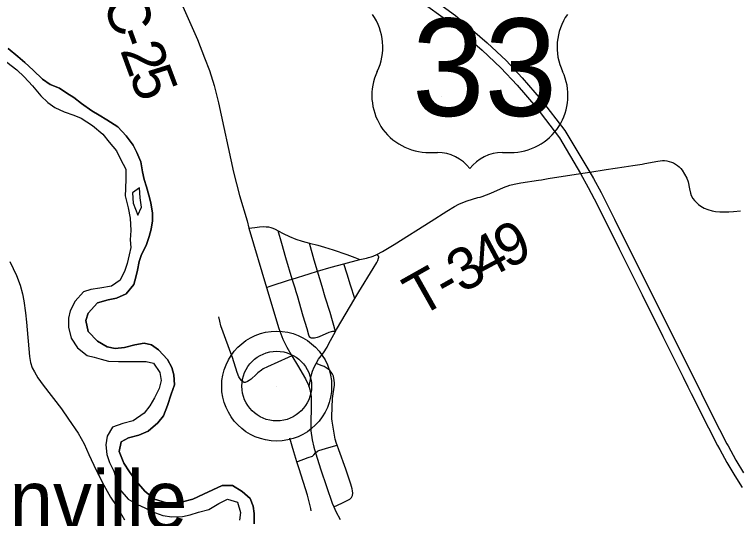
# Model space of a CAD drawing. Extents: x 0 to 34, y 0 to 22.
# Drawn here: x 6.535 to 7.513, y 19.145 to 19.828 of the extents above; entities that cross this region are included whole.
import ezdxf

# ---------------------------------------------------------------- set-up
doc = ezdxf.new("R2010")
doc.units = 0
for name, color, linetype in [('GM_X_County_Road', 7, 'Continuous'), ('GM_X_County_Road_Text', 7, 'Continuous'), ('GM_X_Major_River', 7, 'Continuous'), ('GM_X_Township_Road', 7, 'Continuous'), ('GM_X_Township_Road_Text', 7, 'Continuous'), ('GM_X_Unincorporated', 7, 'Continuous'), ('GM_X_Unincorporated_Location', 7, 'Continuous'), ('GM_X_Unincorporated_Text', 7, 'Continuous'), ('GM_X_US_Location', 7, 'Continuous'), ('GM_X_US_Route', 7, 'Continuous'), ('GM_X_US_Shield', 7, 'Continuous')]:
    doc.layers.add(name, color=color, linetype=linetype)

msp = doc.modelspace()

# ---------------------------------------------------------------- linework, layer by layer
at = {"layer": 'GM_X_County_Road'}
for points in [[(6.7422, 20.01268), (6.73349, 19.99257), (6.72983, 19.98078), (6.72724, 19.96871), (6.72574, 19.95646), (6.72526, 19.94412), (6.72589, 19.9318), (6.72779, 19.91962), (6.73082, 19.90765), (6.73703, 19.89336), (6.74215, 19.88192), (6.74814, 19.87005), (6.76059, 19.84248), (6.78228, 19.79398), (6.79191, 19.76888)], [(6.79191, 19.76888), (6.79833, 19.75214), (6.80482, 19.73182), (6.81063, 19.70809), (6.83112, 19.61417), (6.83931, 19.58275), (6.84956, 19.54826), (6.8518, 19.53845), (6.87567, 19.45833), (6.89225, 19.40271), (6.89759, 19.38823), (6.90302, 19.37716), (6.91006, 19.36545), (6.9174, 19.35322), (6.92859, 19.33449), (6.9326, 19.32597), (6.9331, 19.32438), (6.93449, 19.31993), (6.93587, 19.31056), (6.93617, 19.29805), (6.93544, 19.27322), (6.93577, 19.26399), (6.93743, 19.25177), (6.93979, 19.24193), (6.94181, 19.23412), (6.94937, 19.21129), (6.96439, 19.16599), (6.96661, 19.16101), (6.9694, 19.15472), (6.97549, 19.14401)]]:
    msp.add_lwpolyline(points, dxfattribs=at)
at = {"layer": 'GM_X_Major_River'}
for p, q in [((6.53895, 19.77098), (6.52599, 19.78185)), ((6.54848, 19.76273), (6.53895, 19.77098)), ((6.52426, 19.76327), (6.5376, 19.75278)), ((6.55992, 19.75222), (6.54848, 19.76273)), ((6.5376, 19.75278), (6.54752, 19.74339)), ((6.57252, 19.74021), (6.55992, 19.75222)), ((6.54752, 19.74339), (6.55897, 19.73137)), ((6.58279, 19.73311), (6.57252, 19.74021)), ((6.55897, 19.73137), (6.57006, 19.71783)), ((6.59532, 19.72792), (6.58279, 19.73311)), ((6.60522, 19.72118), (6.59532, 19.72792)), ((6.61473, 19.71559), (6.60522, 19.72118)), ((6.57006, 19.71783), (6.5796, 19.70845)), ((6.62539, 19.70735), (6.61473, 19.71559)), ((6.5796, 19.70845), (6.58912, 19.70171)), ((6.58912, 19.70171), (6.60165, 19.69614)), ((6.63948, 19.69724), (6.62539, 19.70735)), ((6.60165, 19.69614), (6.61494, 19.69134)), ((6.61494, 19.69134), (6.62481, 19.68726)), ((6.64899, 19.69127), (6.63948, 19.69724)), ((6.65964, 19.68492), (6.64899, 19.69127)), ((6.62481, 19.68726), (6.64003, 19.67754)), ((6.67448, 19.67558), (6.65964, 19.68492)), ((6.64003, 19.67754), (6.65414, 19.66554)), ((6.68556, 19.66356), (6.67448, 19.67558)), ((6.65414, 19.66554), (6.66293, 19.65501)), ((6.69513, 19.65076), (6.68556, 19.66356)), ((6.66293, 19.65501), (6.67249, 19.64297)), ((6.70013, 19.64095), (6.69513, 19.65076)), ((6.67249, 19.64297), (6.67826, 19.63204)), ((6.70554, 19.62812), (6.70013, 19.64095)), ((6.67826, 19.63204), (6.68519, 19.61846)), ((6.70792, 19.61488), (6.70554, 19.62812)), ((6.68519, 19.61846), (6.6853, 19.60558)), ((6.70991, 19.60428), (6.70792, 19.61488)), ((6.6853, 19.60558), (6.68466, 19.59193)), ((6.7134, 19.59446), (6.70991, 19.60428)), ((6.68466, 19.59193), (6.68437, 19.58245)), ((6.70395, 19.59286), (6.69743, 19.5885)), ((6.70483, 19.57961), (6.70395, 19.59286)), ((6.71652, 19.58312), (6.7134, 19.59446)), ((6.68437, 19.58245), (6.6883, 19.56581)), ((6.69743, 19.5885), (6.69417, 19.58633)), ((6.69417, 19.58633), (6.69505, 19.57232)), ((6.71888, 19.57291), (6.71652, 19.58312)), ((6.69505, 19.57232), (6.7015, 19.55616)), ((6.70645, 19.56712), (6.70483, 19.57961)), ((6.72128, 19.55891), (6.71888, 19.57291)), ((6.6883, 19.56581), (6.69107, 19.5522)), ((6.7015, 19.55616), (6.70645, 19.56712)), ((6.69107, 19.5522), (6.69197, 19.53553)), ((6.72137, 19.5483), (6.72128, 19.55891)), ((6.71957, 19.5373), (6.72137, 19.5483)), ((6.69197, 19.53553), (6.69095, 19.52264)), ((6.71701, 19.52742), (6.71957, 19.5373)), ((6.69095, 19.52264), (6.69217, 19.51242)), ((6.71258, 19.51488), (6.71701, 19.52742)), ((6.70663, 19.5027), (6.71258, 19.51488)), ((6.69217, 19.51242), (6.68961, 19.50254)), ((6.68961, 19.50254), (6.68706, 19.49077)), ((6.70114, 19.48181), (6.70331, 19.49319)), ((6.70331, 19.49319), (6.70663, 19.5027)), ((6.68706, 19.49077), (6.68412, 19.48127)), ((6.68412, 19.48127), (6.6778, 19.46795)), ((6.69895, 19.47193), (6.70114, 19.48181)), ((6.6778, 19.46795), (6.66576, 19.45988)), ((6.69601, 19.46205), (6.69895, 19.47193)), ((6.6378, 19.45546), (6.62799, 19.45234)), ((6.6499, 19.45709), (6.6378, 19.45546)), ((6.66576, 19.45988), (6.6499, 19.45709)), ((6.68553, 19.44945), (6.69601, 19.46205)), ((6.62799, 19.45234), (6.61675, 19.43973)), ((6.67271, 19.44365), (6.68553, 19.44945)), ((6.61675, 19.43973), (6.61006, 19.42641)), ((6.6343, 19.42322), (6.64704, 19.43735)), ((6.64704, 19.43735), (6.66139, 19.44127)), ((6.66139, 19.44127), (6.67271, 19.44365)), ((6.61006, 19.42641), (6.60749, 19.41653)), ((6.60749, 19.41653), (6.6076, 19.40441)), ((6.63098, 19.41333), (6.6343, 19.42322)), ((6.63414, 19.39858), (6.63098, 19.41333)), ((6.6076, 19.40441), (6.61151, 19.38966)), ((6.64674, 19.38544), (6.63414, 19.39858)), ((6.61151, 19.38966), (6.61995, 19.37648)), ((6.61995, 19.37648), (6.63291, 19.36598)), ((6.66005, 19.37798), (6.64674, 19.38544)), ((6.67066, 19.37542), (6.66005, 19.37798)), ((6.68351, 19.37705), (6.67066, 19.37542)), ((6.69748, 19.38059), (6.68351, 19.37705)), ((6.70995, 19.38298), (6.69748, 19.38059)), ((6.71981, 19.38042), (6.70995, 19.38298)), ((6.72932, 19.37368), (6.71981, 19.38042)), ((6.63291, 19.36598), (6.64238, 19.36379)), ((6.74155, 19.36053), (6.72932, 19.37368)), ((6.64238, 19.36379), (6.65187, 19.36123)), ((6.65187, 19.36123), (6.66173, 19.35829)), ((6.66173, 19.35829), (6.67535, 19.35803)), ((6.67535, 19.35803), (6.68859, 19.35815)), ((6.68859, 19.35815), (6.7026, 19.3579)), ((6.7026, 19.3579), (6.71281, 19.35799)), ((6.71281, 19.35799), (6.72267, 19.35581)), ((6.74731, 19.34997), (6.74155, 19.36053)), ((6.72267, 19.35581), (6.7311, 19.343)), ((6.75042, 19.34015), (6.74731, 19.34997)), ((6.7311, 19.343), (6.73309, 19.33241)), ((6.75092, 19.32651), (6.75042, 19.34015)), ((6.73309, 19.33241), (6.73053, 19.3214)), ((6.73053, 19.3214), (6.72384, 19.30883)), ((6.74649, 19.31359), (6.75092, 19.32651)), ((6.72384, 19.30883), (6.71788, 19.29779)), ((6.74171, 19.29838), (6.74649, 19.31359)), ((6.71788, 19.29779), (6.71002, 19.28824)), ((6.73616, 19.28431), (6.74171, 19.29838)), ((6.71002, 19.28824), (6.69497, 19.27787)), ((6.72867, 19.27477), (6.73616, 19.28431)), ((6.66743, 19.26891), (6.65996, 19.25709)), ((6.681, 19.27396), (6.66743, 19.26891)), ((6.69497, 19.27787), (6.681, 19.27396)), ((6.71552, 19.26366), (6.72867, 19.27477)), ((6.70271, 19.25824), (6.71552, 19.26366)), ((6.65996, 19.25709), (6.65818, 19.24495)), ((6.67604, 19.23602), (6.67895, 19.24931)), ((6.67895, 19.24931), (6.68874, 19.2547)), ((6.68874, 19.2547), (6.70271, 19.25824)), ((6.65818, 19.24495), (6.65942, 19.23208)), ((6.65942, 19.23208), (6.6633, 19.22112)), ((6.68261, 19.22016), (6.67604, 19.23602)), ((6.6633, 19.22112), (6.66908, 19.20943)), ((6.69028, 19.20848), (6.68261, 19.22016)), ((6.66908, 19.20943), (6.67298, 19.19658)), ((6.69985, 19.19569), (6.69028, 19.20848)), ((6.67298, 19.19658), (6.67724, 19.18487)), ((6.71093, 19.18253), (6.69985, 19.19569)), ((6.81568, 19.18992), (6.80286, 19.18412)), ((6.82968, 19.19005), (6.81568, 19.18992)), ((6.84261, 19.18221), (6.82968, 19.19005)), ((6.67724, 19.18487), (6.68833, 19.17171)), ((6.72427, 19.17166), (6.71093, 19.18253)), ((6.80286, 19.18412), (6.79043, 19.17832)), ((6.85367, 19.17246), (6.84261, 19.18221)), ((6.68833, 19.17171), (6.70088, 19.16424)), ((6.74021, 19.1665), (6.72427, 19.17166)), ((6.77573, 19.17174), (6.76214, 19.16821)), ((6.79043, 19.17832), (6.77573, 19.17174)), ((6.81097, 19.16563), (6.82303, 19.17142)), ((6.82303, 19.17142), (6.83631, 19.16737)), ((6.85754, 19.16226), (6.85367, 19.17246)), ((6.70088, 19.16424), (6.71076, 19.15979)), ((6.75232, 19.16585), (6.74021, 19.1665)), ((6.76214, 19.16821), (6.75232, 19.16585)), ((6.7978, 19.15755), (6.81097, 19.16563)), ((6.83631, 19.16737), (6.84059, 19.15339)), ((6.85914, 19.15242), (6.85754, 19.16226)), ((6.71076, 19.15979), (6.72063, 19.15495)), ((6.72063, 19.15495), (6.73544, 19.1494)), ((6.77251, 19.1505), (6.78345, 19.15401)), ((6.78345, 19.15401), (6.7978, 19.15755)), ((6.84059, 19.15339), (6.83917, 19.14315)), ((6.85888, 19.1384), (6.85914, 19.15242)), ((6.73544, 19.1494), (6.74756, 19.14762)), ((6.74756, 19.14762), (6.76194, 19.14813)), ((6.76194, 19.14813), (6.77251, 19.1505))]:
    msp.add_line(p, q, dxfattribs=at)
for points in [[(6.52599, 19.78185), (6.53895, 19.77098), (6.54848, 19.76273), (6.55992, 19.75222), (6.57252, 19.74021), (6.58279, 19.73311), (6.59532, 19.72792), (6.60522, 19.72118), (6.61473, 19.71559), (6.62539, 19.70735), (6.63948, 19.69724), (6.64899, 19.69127), (6.65964, 19.68492), (6.67448, 19.67558), (6.68556, 19.66356), (6.69513, 19.65076), (6.70013, 19.64095), (6.70554, 19.62812), (6.70792, 19.61488), (6.70991, 19.60428), (6.7134, 19.59446), (6.71652, 19.58312), (6.71888, 19.57291), (6.72128, 19.55891), (6.72137, 19.5483), (6.71957, 19.5373), (6.71701, 19.52742), (6.71258, 19.51488), (6.70663, 19.5027), (6.70331, 19.49319), (6.70114, 19.48181), (6.69895, 19.47193), (6.69601, 19.46205), (6.68553, 19.44945), (6.67271, 19.44365), (6.66139, 19.44127), (6.64704, 19.43735), (6.6343, 19.42322), (6.63098, 19.41333), (6.63414, 19.39858), (6.64674, 19.38544), (6.66005, 19.37798), (6.67066, 19.37542), (6.68351, 19.37705), (6.69748, 19.38059), (6.70995, 19.38298), (6.71981, 19.38042), (6.72932, 19.37368), (6.74155, 19.36053), (6.74731, 19.34997), (6.75042, 19.34015), (6.75092, 19.32651), (6.74649, 19.31359), (6.74171, 19.29838), (6.73616, 19.28431), (6.72867, 19.27477), (6.71552, 19.26366), (6.70271, 19.25824), (6.68874, 19.2547), (6.67895, 19.24931), (6.67604, 19.23602), (6.68261, 19.22016), (6.69028, 19.20848), (6.69985, 19.19569), (6.71093, 19.18253), (6.72427, 19.17166), (6.74021, 19.1665), (6.75232, 19.16585), (6.76214, 19.16821), (6.77573, 19.17174), (6.79043, 19.17832), (6.80286, 19.18412), (6.81568, 19.18992), (6.82968, 19.19005), (6.84261, 19.18221), (6.85367, 19.17246), (6.85754, 19.16226), (6.85914, 19.15242), (6.85888, 19.1384)], [(6.52426, 19.76327), (6.5376, 19.75278), (6.54752, 19.74339), (6.55897, 19.73137), (6.57006, 19.71783), (6.5796, 19.70845), (6.58912, 19.70171), (6.60165, 19.69614), (6.61494, 19.69134), (6.62481, 19.68726), (6.64003, 19.67754), (6.65414, 19.66554), (6.66293, 19.65501), (6.67249, 19.64297), (6.67826, 19.63204), (6.68519, 19.61846), (6.6853, 19.60558), (6.68466, 19.59193), (6.68437, 19.58245), (6.6883, 19.56581), (6.69107, 19.5522), (6.69197, 19.53553), (6.69095, 19.52264), (6.69217, 19.51242), (6.68961, 19.50254), (6.68706, 19.49077), (6.68412, 19.48127), (6.6778, 19.46795), (6.66576, 19.45988), (6.6499, 19.45709), (6.6378, 19.45546), (6.62799, 19.45234), (6.61675, 19.43973), (6.61006, 19.42641), (6.60749, 19.41653), (6.6076, 19.40441), (6.61151, 19.38966), (6.61995, 19.37648), (6.63291, 19.36598), (6.64238, 19.36379), (6.65187, 19.36123), (6.66173, 19.35829), (6.67535, 19.35803), (6.68859, 19.35815), (6.7026, 19.3579), (6.71281, 19.35799), (6.72267, 19.35581), (6.7311, 19.343), (6.73309, 19.33241), (6.73053, 19.3214), (6.72384, 19.30883), (6.71788, 19.29779), (6.71002, 19.28824), (6.69497, 19.27787), (6.681, 19.27396), (6.66743, 19.26891), (6.65996, 19.25709), (6.65818, 19.24495), (6.65942, 19.23208), (6.6633, 19.22112), (6.66908, 19.20943), (6.67298, 19.19658), (6.67724, 19.18487), (6.68833, 19.17171), (6.70088, 19.16424), (6.71076, 19.15979), (6.72063, 19.15495), (6.73544, 19.1494), (6.74756, 19.14762), (6.76194, 19.14813), (6.77251, 19.1505), (6.78345, 19.15401), (6.7978, 19.15755), (6.81097, 19.16563), (6.82303, 19.17142), (6.83631, 19.16737), (6.84059, 19.15339), (6.83917, 19.14315)]]:
    msp.add_lwpolyline(points, dxfattribs=at)
at = {"layer": 'GM_X_Township_Road'}
for points in [[(7.24383, 19.60333), (7.2478, 19.60388), (7.25703, 19.60572), (7.30054, 19.61243), (7.31318, 19.6144), (7.33541, 19.61784), (7.35975, 19.62132), (7.3714, 19.62315), (7.38415, 19.62528), (7.38782, 19.62597)], [(7.38782, 19.62597), (7.40524, 19.62926), (7.40829, 19.62969), (7.41138, 19.62994), (7.41449, 19.62991), (7.41757, 19.62956), (7.4206, 19.62888), (7.42356, 19.62793), (7.42641, 19.62671), (7.42914, 19.62524), (7.4317, 19.6235), (7.43406, 19.6215), (7.43621, 19.61927), (7.4381, 19.61682), (7.44141, 19.61156), (7.4445, 19.60632), (7.4461, 19.60128), (7.448, 19.59154), (7.44932, 19.58577), (7.45047, 19.58248), (7.45245, 19.57877), (7.455, 19.57572), (7.45739, 19.57316), (7.45968, 19.57119)], [(7.02497, 19.50302), (7.03244, 19.50694), (7.04847, 19.51652), (7.09859, 19.5481), (7.11957, 19.56155), (7.13026, 19.56794), (7.13577, 19.57084), (7.14147, 19.57334), (7.14731, 19.57544), (7.1618, 19.57987), (7.16464, 19.58056), (7.1675, 19.58146), (7.17909, 19.58592), (7.19616, 19.59341), (7.20492, 19.59652), (7.21089, 19.59818), (7.22002, 19.60004), (7.24383, 19.60333)], [(7.45968, 19.57119), (7.46044, 19.57053), (7.46341, 19.56838), (7.46786, 19.5655), (7.47289, 19.5636), (7.47857, 19.56196), (7.48343, 19.56113), (7.48895, 19.5608), (7.4945, 19.56073), (7.50126, 19.56054), (7.50765, 19.56092), (7.51692, 19.56208)], [(6.8518, 19.53845), (6.85982, 19.5395), (6.86598, 19.54032), (6.87221, 19.5406), (6.87532, 19.54051), (6.87842, 19.54019), (6.88145, 19.53952), (6.88441, 19.5386), (6.88726, 19.53735), (6.89149, 19.53504), (6.89819, 19.53138), (6.90658, 19.5273), (6.91521, 19.52374), (6.92407, 19.52081), (6.9338, 19.51825), (6.94515, 19.51528), (6.95417, 19.51283), (6.96603, 19.50907), (6.98439, 19.50267), (6.99508, 19.4989), (7.0021, 19.49617)], [(6.91035, 19.46959), (6.90159, 19.49816), (6.89617, 19.5179), (6.89149, 19.53504)], [(6.96902, 19.39876), (6.96172, 19.42426), (6.95516, 19.44488), (6.95079, 19.4597), (6.94472, 19.48007), (6.94018, 19.49527), (6.9338, 19.51825)], [(6.87567, 19.45833), (6.88046, 19.45989), (6.90663, 19.46844), (6.91035, 19.46959), (6.93344, 19.47667), (6.94472, 19.48007), (6.96324, 19.48565), (6.98015, 19.49021), (7.0021, 19.49617), (7.01076, 19.49777), (7.01381, 19.49855), (7.01709, 19.49953), (7.02015, 19.50078), (7.02497, 19.50302)], [(6.9331, 19.32438), (6.93365, 19.32697), (6.93616, 19.33878), (6.93685, 19.34182), (6.9378, 19.34478), (6.94024, 19.35052), (6.94296, 19.35543), (6.94586, 19.36104), (6.94971, 19.36544), (6.953, 19.36983), (6.95794, 19.37724), (6.96014, 19.38246), (6.96902, 19.39876), (6.97045, 19.40137), (6.99506, 19.44313), (7.00055, 19.45232), (7.02015, 19.48401), (7.02477, 19.49215), (7.02616, 19.49493), (7.02721, 19.4979), (7.02744, 19.49901), (7.02748, 19.49947), (7.02743, 19.49991), (7.02729, 19.50029), (7.02707, 19.50066), (7.0262, 19.50165), (7.02497, 19.50302)], [(6.52812, 19.49333), (6.53738, 19.47453), (6.5423, 19.46143), (6.5456, 19.44946), (6.5474, 19.44014), (6.54932, 19.42381), (6.55079, 19.41121), (6.55478, 19.36483), (6.55633, 19.35658), (6.55857, 19.34956), (6.56152, 19.34378), (6.56624, 19.33599), (6.57343, 19.32594), (6.59811, 19.29376), (6.60765, 19.27974), (6.62066, 19.261), (6.62874, 19.24643), (6.63537, 19.2322), (6.6451, 19.21089), (6.6553, 19.19046), (6.66468, 19.17424), (6.67288, 19.1615), (6.68334, 19.14355)], [(6.99506, 19.44313), (6.98935, 19.46132), (6.98472, 19.47643), (6.98015, 19.49021)], [(6.96902, 19.39876), (6.96516, 19.3986), (6.9631, 19.39808), (6.96, 19.39703), (6.94694, 19.39151), (6.94438, 19.39054), (6.94233, 19.38992), (6.94043, 19.38966), (6.93868, 19.38953), (6.93717, 19.3896), (6.93598, 19.38979), (6.93484, 19.39027), (6.93408, 19.39094), (6.93345, 19.39208), (6.93288, 19.39377), (6.93057, 19.40217), (6.92542, 19.41924), (6.91746, 19.44702), (6.91588, 19.45245), (6.91446, 19.45711), (6.91035, 19.46959)], [(6.91006, 19.36545), (6.90497, 19.36319), (6.87681, 19.35064), (6.87132, 19.34784), (6.86869, 19.34626), (6.86377, 19.3426), (6.86144, 19.3406), (6.85469, 19.33428), (6.85233, 19.33234), (6.84973, 19.33078), (6.84689, 19.32962), (6.84553, 19.32968), (6.84472, 19.32988), (6.84396, 19.33029), (6.84164, 19.33224), (6.83983, 19.33468), (6.83835, 19.33731), (6.83601, 19.34298), (6.82941, 19.36339), (6.82756, 19.3692), (6.81679, 19.39777), (6.81385, 19.40648), (6.81237, 19.41242), (6.81113, 19.41843)], [(6.96661, 19.16101), (6.97181, 19.16365), (6.97854, 19.16675), (6.98584, 19.1701), (6.98847, 19.17171), (6.99059, 19.17389), (6.99188, 19.17665), (6.99233, 19.1797), (6.99213, 19.18277), (6.99155, 19.18581), (6.98988, 19.19177), (6.98294, 19.21221), (6.97337, 19.23829), (6.97111, 19.24451), (6.97032, 19.24701), (6.96877, 19.25296), (6.96438, 19.27725), (6.9641, 19.2803), (6.96409, 19.28339), (6.96488, 19.30795), (6.96525, 19.31095), (6.96688, 19.31998), (6.96762, 19.32609), (6.96767, 19.32917), (6.96737, 19.33217), (6.96628, 19.33819), (6.96507, 19.34094), (6.96337, 19.34348), (6.96133, 19.34579), (6.95903, 19.34782), (6.95649, 19.34957), (6.95379, 19.35103), (6.95094, 19.35218), (6.94296, 19.35543)], [(6.93611, 19.15571), (6.9356, 19.15878), (6.93357, 19.16789), (6.93103, 19.17688), (6.91966, 19.21251), (6.91686, 19.22235), (6.91282, 19.23582), (6.90738, 19.25437)], [(6.91686, 19.22235), (6.93211, 19.2279), (6.93784, 19.23), (6.9389, 19.23059), (6.93989, 19.23141), (6.94181, 19.23412), (6.9448, 19.23679), (6.9465, 19.23757), (6.96, 19.24152), (6.97111, 19.24451)]]:
    msp.add_lwpolyline(points, dxfattribs=at)
at = {"layer": 'GM_X_Unincorporated'}
for radius in [0.0744, 0.04716]:
    msp.add_circle((6.88943, 19.32466), radius, dxfattribs=at)
at = {"layer": 'GM_X_Unincorporated_Location'}
msp.add_line((6.88943, 19.32466), (6.88943, 19.32466), dxfattribs=at)
at = {"layer": 'GM_X_US_Route'}
msp.add_line((7.44598, 19.32361), (7.45041, 19.31478), dxfattribs=at)
for points in [[(6.75923, 20.06863), (6.7661, 20.06413), (6.77511, 20.05824), (6.89424, 19.97594), (7.0163, 19.89172), (7.08144, 19.84796), (7.12421, 19.81671), (7.16731, 19.77953), (7.19264, 19.75551), (7.21468, 19.73215), (7.24002, 19.70255), (7.27226, 19.66076), (7.30054, 19.61243), (7.31101, 19.59365), (7.32322, 19.57056), (7.35308, 19.51045), (7.38401, 19.44812), (7.41202, 19.39196), (7.43935, 19.33686), (7.44598, 19.32361)], [(7.0886, 19.85784), (7.13136, 19.82658), (7.17446, 19.78941), (7.19979, 19.76539), (7.22184, 19.74203), (7.24717, 19.71242), (7.27941, 19.67064), (7.31318, 19.6144), (7.31814, 19.60571), (7.32846, 19.5866), (7.34667, 19.55057), (7.38597, 19.47158), (7.44992, 19.3438), (7.47898, 19.28539), (7.49876, 19.24664), (7.50022, 19.24395)], [(7.45041, 19.31478), (7.47385, 19.26798), (7.48621, 19.24406)], [(7.48621, 19.24406), (7.48896, 19.23875), (7.4986, 19.22139), (7.50939, 19.20327), (7.51941, 19.18759)], [(7.50022, 19.24395), (7.5109, 19.22421), (7.521, 19.20704)]]:
    msp.add_lwpolyline(points, dxfattribs=at)
at = {"layer": 'GM_X_US_Shield'}
for p, q in [((7.096, 19.64102), (7.10699, 19.64102)), ((7.19488, 19.64102), (7.20587, 19.64102))]:
    msp.add_line(p, q, dxfattribs=at)
for centre, radius, start, end in [((6.9561, 19.78368), 0.0769, 334.54712, 35.00093), ((7.34577, 19.78368), 0.0769, 144.99907, 205.45288), ((7.09515, 19.71792), 0.0769, 154.83192, 270.63826), ((7.20673, 19.71792), 0.0769, 269.36174, 25.16808), ((7.10699, 19.58609), 0.05493, 36.8699, 90), ((7.19488, 19.58609), 0.05493, 90, 143.1301)]:
    msp.add_arc(centre, radius, start, end, dxfattribs=at)

# ---------------------------------------------------------------- texts
at = {"layer": 'GM_X_County_Road_Text'}
for s, rotation, p in [('C', 289.99645, (6.65317, 19.84544)), ('-', 290.02086, (6.66913, 19.80157)), ('2', 290.16712, (6.67717, 19.77949)), ('5', 290.58246, (6.6894, 19.74622))]:
    msp.add_text(s, height=0.05682, rotation=rotation, dxfattribs=at).set_placement(p)
at = {"layer": 'GM_X_Township_Road_Text'}
for s, rotation, p in [('9', 25.41524, (7.20063, 19.48265)), ('4', 28.09667, (7.17038, 19.46649)), ('3', 28.95807, (7.13995, 19.44965)), ('T', 29.39137, (7.08267, 19.41743)), ('-', 29.29567, (7.11968, 19.43827))]:
    msp.add_text(s, height=0.05682, rotation=rotation, dxfattribs=at).set_placement(p)
at = {"layer": 'GM_X_Unincorporated_Text'}
msp.add_text('Haydenville', height=0.0789773, rotation=0.00001, dxfattribs=at).set_placement((6.2226, 19.13164))
at = {"layer": 'GM_X_US_Location'}
for s, p in [('0', (7.15086, 19.75534)), ('/', (7.15088, 19.75534))]:
    msp.add_text(s, height=0.000189, dxfattribs=at).set_placement(p)
msp.add_text('33', height=0.000189, rotation=0.00001, dxfattribs=at).set_placement((7.11177, 19.71613))
at = {"layer": 'GM_X_US_Shield'}
msp.add_text('33', height=0.131836, dxfattribs=at).set_placement((7.07266, 19.69046))

doc.saveas('drawing.dxf')
